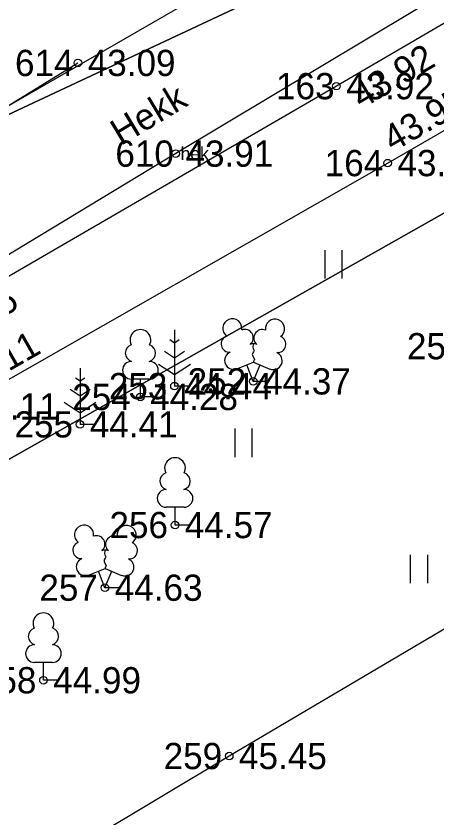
# Model space of a CAD drawing. Extents: x 505800 to 507326, y 6540058 to 6542128.
# Drawn here: x 506375.21 to 506386.44, y 6540333.29 to 6540354.69 of the extents above; entities that cross this region are included whole.
import ezdxf

# ---------------------------------------------------------------- set-up
doc = ezdxf.new("R2010")
doc.units = 0
for name, color, linetype in [('AED', 7, 'Continuous'), ('HALJASTUS', 7, 'Continuous'), ('KORGUS-EH2000', 7, 'Continuous'), ('MAAMUDEL', 7, 'Continuous'), ('MOOTKORG-EH2000', 7, 'Continuous'), ('MOOTMPUNKT', 7, 'Continuous'), ('MOOTNR', 7, 'Continuous'), ('MOOTPIIR', 7, 'Continuous'), ('PIIR', 7, 'Continuous'), ('PUU', 7, 'Continuous'), ('TEE', 7, 'Continuous')]:
    doc.layers.add(name, color=color, linetype=linetype)

msp = doc.modelspace()

# ---------------------------------------------------------------- linework, layer by layer
at = {"layer": 'AED'}
msp.add_lwpolyline([(506368.771, 6540350.837), (506369.577, 6540348.962), (506376.866, 6540353.439)], dxfattribs=at)
at = {"layer": 'HALJASTUS'}
for p, q in [((506383.448, 6540348.446), (506383.448, 6540347.685)), ((506383.903, 6540348.446), (506383.903, 6540347.685)), ((506381.046, 6540343.679), (506381.046, 6540342.917)), ((506381.501, 6540343.679), (506381.501, 6540342.917)), ((506385.731, 6540340.313), (506385.731, 6540339.552)), ((506386.186, 6540340.313), (506386.186, 6540339.552))]:
    msp.add_line(p, q, dxfattribs=at)
msp.add_lwpolyline([(506383.074, 6540362.871), (506387.104, 6540358.456), (506388.363, 6540356.347), (506379.473, 6540351.019), (506371.247, 6540346.037), (506370.193, 6540346.236), (506368.863, 6540348.749), (506383.542, 6540357.221), (506381.795, 6540361.969), (506383.074, 6540362.871)], dxfattribs=at)
at = {"layer": 'KORGUS-EH2000'}
for centre in [(506376.866, 6540353.439), (506383.759, 6540352.819), (506379.473, 6540351.019), (506385.127, 6540350.766), (506381.542, 6540344.94), (506379.439, 6540344.814), (506378.532, 6540344.525), (506376.922, 6540343.793), (506379.455, 6540341.106), (506377.586, 6540339.434), (506375.945, 6540336.964), (506380.901, 6540334.942)]:
    msp.add_circle(centre, 0.1, dxfattribs=at)
at = {"layer": 'MOOTMPUNKT'}
for centre in [(506376.866, 6540353.439), (506383.759, 6540352.819), (506379.473, 6540351.019), (506385.127, 6540350.766), (506381.542, 6540344.94), (506379.439, 6540344.814), (506378.532, 6540344.525), (506376.922, 6540343.793), (506379.455, 6540341.106), (506377.586, 6540339.434), (506375.945, 6540336.964), (506380.901, 6540334.942)]:
    msp.add_circle(centre, 0.1, dxfattribs=at)
at = {"layer": 'MOOTPIIR'}
msp.add_lwpolyline([(506495.183, 6540386.603), (506455.807, 6540378.751), (506413.936, 6540356.957), (506411.426, 6540354.112), (506402.307, 6540351.523), (506391.999, 6540341.498), (506380.901, 6540334.942), (506360.247, 6540322.568), (506353.013, 6540324.95), (506332.133, 6540309.036), (506315.598, 6540297.889), (506301.375, 6540281.904), (506292.827, 6540267.673), (506286.653, 6540264.508), (506248.469, 6540250.071)], dxfattribs=at)
at = {"layer": 'PIIR'}
msp.add_lwpolyline([(506326.14, 6540370.11), (506324.04, 6540375.18), (506354.05, 6540393.57), (506395.54, 6540418.74), (506427.6, 6540438.79), (506429.21, 6540436.36), (506458.7, 6540391.28), (506340.34, 6540335.82)], close=True, dxfattribs=at)
for points in [[(506215.95, 6540254.34), (506268.55, 6540273.9), (506274.54, 6540277.85), (506304.35, 6540308.95), (506340.34, 6540335.82), (506458.7, 6540391.28), (506563.96, 6540420.02)], [(506497.85, 6540391.32), (506462.8, 6540384.69), (506453.27, 6540382.76), (506413.82, 6540364.84), (506374.55, 6540342.6), (506353.59, 6540332.53), (506318.07, 6540309.28), (506308, 6540301.95), (506281.65, 6540275.05), (506272.39, 6540267.75), (506224.13, 6540249.92)], [(506224.13, 6540249.92), (506272.39, 6540267.75), (506281.65, 6540275.05), (506308, 6540301.95), (506318.07, 6540309.28), (506353.59, 6540332.53), (506374.55, 6540342.6), (506413.82, 6540364.84), (506453.27, 6540382.76), (506462.8, 6540384.69), (506495.14, 6540337.45), (506342.85, 6540237.27), (506260.72, 6540195.9), (506215.68, 6540179.69)]]:
    msp.add_lwpolyline(points, dxfattribs=at)
at = {"layer": 'PUU'}
for p, q in [((506379.439, 6540346.314), (506379.439, 6540344.814)), ((506379.439, 6540345.964), (506379.315, 6540346.047)), ((506379.564, 6540346.047), (506379.439, 6540345.964)), ((506379.439, 6540345.564), (506379.173, 6540345.741)), ((506379.706, 6540345.741), (506379.439, 6540345.564)), ((506381.102, 6540345.275), (506381.547, 6540345.45)), ((506381.547, 6540345.45), (506381.987, 6540345.27)), ((506376.922, 6540345.293), (506376.922, 6540343.793)), ((506379.015, 6540345.403), (506379.439, 6540345.12)), ((506379.439, 6540345.12), (506379.864, 6540345.403)), ((506381.542, 6540344.94), (506381.367, 6540345.38)), ((506381.542, 6540344.94), (506381.722, 6540345.38)), ((506376.922, 6540344.943), (506376.797, 6540345.026)), ((506377.046, 6540345.026), (506376.922, 6540344.943)), ((506378.772, 6540345), (506378.292, 6540345)), ((506378.532, 6540344.525), (506378.532, 6540345)), ((506379.799, 6540344.814), (506379.439, 6540344.814)), ((506381.922, 6540344.94), (506381.542, 6540344.94)), ((506376.922, 6540344.543), (506376.655, 6540344.721)), ((506377.188, 6540344.721), (506376.922, 6540344.543)), ((506376.498, 6540344.382), (506376.922, 6540344.099)), ((506376.922, 6540344.099), (506377.346, 6540344.382)), ((506378.912, 6540344.525), (506378.532, 6540344.525)), ((506377.282, 6540343.793), (506376.922, 6540343.793)), ((506379.695, 6540341.581), (506379.215, 6540341.581)), ((506379.455, 6540341.106), (506379.455, 6540341.581)), ((506379.835, 6540341.106), (506379.455, 6540341.106)), ((506377.146, 6540339.769), (506377.591, 6540339.944)), ((506377.586, 6540339.434), (506377.411, 6540339.874)), ((506377.586, 6540339.434), (506377.766, 6540339.874)), ((506377.591, 6540339.944), (506378.031, 6540339.764)), ((506377.966, 6540339.434), (506377.586, 6540339.434)), ((506376.185, 6540337.439), (506375.705, 6540337.439)), ((506375.945, 6540336.964), (506375.945, 6540337.439)), ((506376.325, 6540336.964), (506375.945, 6540336.964))]:
    msp.add_line(p, q, dxfattribs=at)
for points in [[(506381.547, 6540345.945), (506381.527, 6540345.87), (506381.527, 6540345.85), (506381.537, 6540345.82), (506381.557, 6540345.785), (506381.562, 6540345.765), (506381.547, 6540345.73), (506381.522, 6540345.68), (506381.517, 6540345.655), (506381.522, 6540345.64), (506381.532, 6540345.61), (506381.567, 6540345.55), (506381.572, 6540345.53), (506381.567, 6540345.51), (506381.552, 6540345.475), (506381.547, 6540345.45)], [(506377.591, 6540340.439), (506377.571, 6540340.364), (506377.571, 6540340.344), (506377.581, 6540340.314), (506377.601, 6540340.279), (506377.606, 6540340.259), (506377.591, 6540340.224), (506377.566, 6540340.174), (506377.561, 6540340.149), (506377.566, 6540340.134), (506377.576, 6540340.104), (506377.611, 6540340.044), (506377.616, 6540340.024), (506377.611, 6540340.004), (506377.596, 6540339.969), (506377.591, 6540339.944)]]:
    msp.add_lwpolyline(points, dxfattribs=at)
for centre, radius, start, end in [((506380.984, 6540346.354), 0.256, 111.5027, 232.5173), ((506380.984, 6540346.354), 0.256, 350.4856, 111.5002), ((506382.12, 6540346.345), 0.256, 67.6168, 188.6314), ((506382.12, 6540346.345), 0.256, 306.5997, 67.6143), ((506378.532, 6540346.045), 0.277, 332.5799, 207.4201), ((506381.319, 6540346.103), 0.224, 308.5041, 111.5725), ((506381.782, 6540346.099), 0.225, 67.7016, 230.5126), ((506380.911, 6540345.942), 0.224, 111.4304, 274.4987), ((506382.188, 6540345.933), 0.224, 264.6183, 67.6866), ((506378.362, 6540345.697), 0.233, 109.0217, 253.1415), ((506378.702, 6540345.697), 0.233, 286.8508, 70.9859), ((506381.546, 6540345.707), 0.237, 66.7655, 111.5015), ((506381.015, 6540345.498), 0.237, 111.5014, 291.5004), ((506382.076, 6540345.49), 0.237, 247.6166, 67.6155), ((506378.295, 6540345.237), 0.238, 90.0016, 269.3953), ((506378.77, 6540345.237), 0.238, 270.6047, 89.9984), ((506379.455, 6540342.626), 0.277, 332.5799, 207.4201), ((506379.285, 6540342.278), 0.233, 109.0217, 253.1415), ((506379.626, 6540342.278), 0.233, 286.8508, 70.9859), ((506379.218, 6540341.818), 0.238, 90.0016, 269.3953), ((506379.693, 6540341.818), 0.238, 270.6047, 89.9984), ((506377.029, 6540340.848), 0.256, 111.5027, 232.5173), ((506377.029, 6540340.848), 0.256, 350.4856, 111.5002), ((506378.165, 6540340.839), 0.256, 67.6168, 188.6314), ((506378.165, 6540340.839), 0.256, 306.5997, 67.6143), ((506377.363, 6540340.597), 0.224, 308.5041, 111.5725), ((506377.826, 6540340.593), 0.225, 67.7016, 230.5126), ((506376.955, 6540340.436), 0.224, 111.4304, 274.4987), ((506378.232, 6540340.427), 0.224, 264.6183, 67.6866), ((506377.59, 6540340.201), 0.237, 66.7655, 111.5015), ((506377.059, 6540339.992), 0.237, 111.5014, 291.5004), ((506378.121, 6540339.984), 0.237, 247.6166, 67.6155), ((506375.945, 6540338.484), 0.277, 332.5799, 207.4201), ((506375.775, 6540338.136), 0.233, 109.0217, 253.1415), ((506376.116, 6540338.136), 0.233, 286.8508, 70.9859), ((506375.708, 6540337.676), 0.238, 90.0016, 269.3953), ((506376.183, 6540337.676), 0.238, 270.6047, 89.9984)]:
    msp.add_arc(centre, radius, start, end, dxfattribs=at)
at = {"layer": 'TEE'}
for points in [[(506478.706, 6540392.058), (506464.091, 6540389.4), (506454.678, 6540387.173), (506446.264, 6540384.451), (506435.18, 6540379.372), (506420.092, 6540372.182), (506407.957, 6540366.228), (506394.897, 6540359.329), (506383.759, 6540352.819), (506372.647, 6540346.37), (506363.224, 6540341.99), (506352.182, 6540336.393), (506347.174, 6540333.201), (506340.898, 6540329.111), (506329.323, 6540321.237)], [(506479.167, 6540389.797), (506464.651, 6540387.028), (506455.166, 6540384.708), (506447.071, 6540382.035), (506436.402, 6540377.232), (506421.232, 6540370.083), (506409.03, 6540364.194), (506396.144, 6540357.137), (506385.127, 6540350.766), (506373.749, 6540344.271), (506364.374, 6540339.718), (506353.506, 6540334.212), (506348.479, 6540331.101), (506342.338, 6540327.065), (506330.786, 6540319.25)]]:
    msp.add_lwpolyline(points, dxfattribs=at)

# ---------------------------------------------------------------- texts
at = {"layer": 'HALJASTUS'}
msp.add_text('Hekk', height=0.7, rotation=30.9694, dxfattribs=at).set_placement((506378.01, 6540351.219))
at = {"layer": 'KORGUS-EH2000'}
for s, p in [(' 43.09', (506376.866, 6540353.089)), (' 44.37', (506381.542, 6540344.59)), (' 44.99', (506375.945, 6540336.614)), (' 45.45', (506380.901, 6540334.592))]:
    msp.add_text(s, height=0.7, dxfattribs=at).set_placement(p)
for s, rotation, p in [(' 43.92', 30.3075, (506384.201, 6540352.064)), (' 43.95', 30.0411, (506385.04, 6540350.918)), (' 44.05', 30.1302, (506373.086, 6540345.613)), (' 44.11', 29.7195, (506373.662, 6540344.423))]:
    msp.add_text(s, height=0.7, rotation=rotation, dxfattribs=at).set_placement(p)
at = {"layer": 'MAAMUDEL'}
msp.add_text(' hek', height=0.35, dxfattribs=at).set_placement((506379.473, 6540350.844))
at = {"layer": 'MOOTKORG-EH2000'}
for s, p in [(' 43.09', (506376.866, 6540353.089)), (' 43.92', (506383.759, 6540352.469)), (' 43.91', (506379.473, 6540350.669)), (' 43.95', (506385.127, 6540350.416)), (' 44.37', (506381.542, 6540344.59)), (' 44.44', (506379.439, 6540344.464)), (' 44.28', (506378.532, 6540344.175)), (' 44.11', (506373.749, 6540343.921)), (' 44.41', (506376.922, 6540343.443)), (' 44.57', (506379.455, 6540340.756)), (' 44.63', (506377.586, 6540339.084)), (' 44.99', (506375.945, 6540336.614)), (' 45.45', (506380.901, 6540334.592))]:
    msp.add_text(s, height=0.7, dxfattribs=at).set_placement(p)
at = {"layer": 'MOOTNR'}
for s, p in [('614 ', (506375.186, 6540353.089)), ('163 ', (506382.149, 6540352.469)), ('610 ', (506377.863, 6540350.669)), ('164 ', (506383.447, 6540350.416)), ('251 ', (506385.641, 6540345.53)), ('252 ', (506379.792, 6540344.59)), ('253 ', (506377.689, 6540344.464)), ('254 ', (506376.713, 6540344.175)), ('255 ', (506375.172, 6540343.443)), ('256 ', (506377.706, 6540340.756)), ('257 ', (506375.836, 6540339.084)), ('258 ', (506374.196, 6540336.614)), ('259 ', (506379.151, 6540334.592))]:
    msp.add_text(s, height=0.7, dxfattribs=at).set_placement(p)

doc.saveas('drawing.dxf')
